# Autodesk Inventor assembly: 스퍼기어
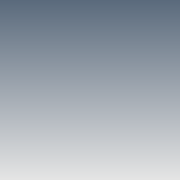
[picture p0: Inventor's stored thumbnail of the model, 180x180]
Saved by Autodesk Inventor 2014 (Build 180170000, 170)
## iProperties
Created: 2018-04
Part Number: 스퍼기어
Document SubType Name: Assembly
Designer: user
Author: user
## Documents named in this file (1)
- C:\Users\user\Desktop\스퍼기어.iam
